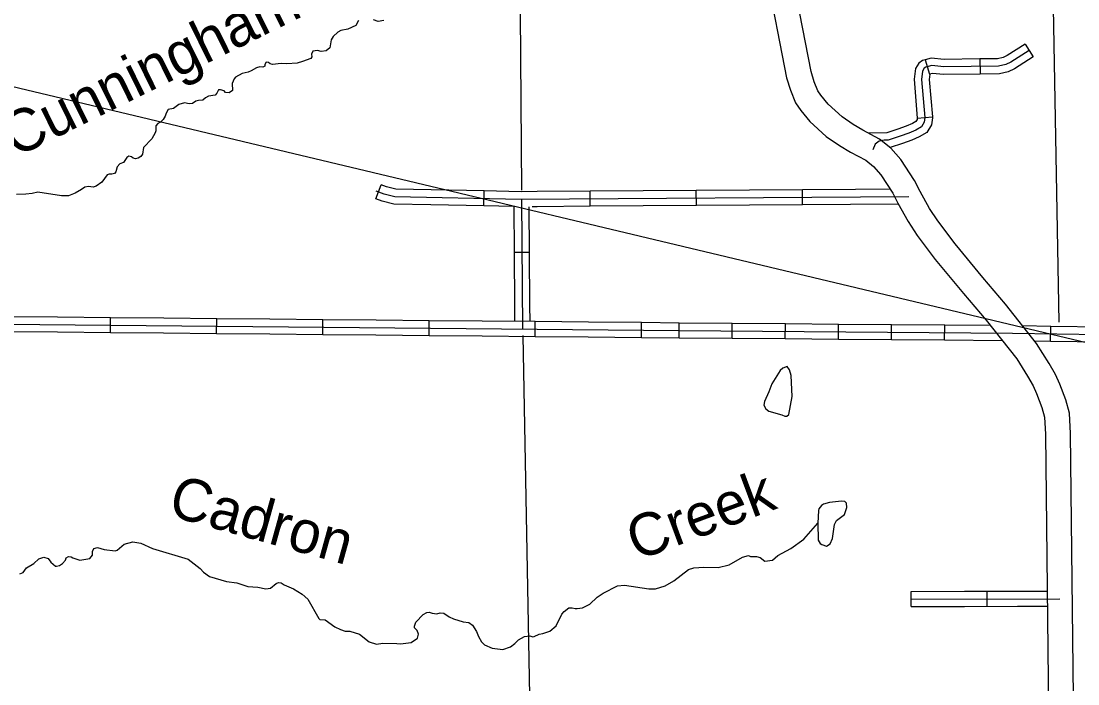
# Model space of a CAD drawing. Extents: x 1212896 to 1368412, y 378476 to 478763.
# Drawn here: x 1289328 to 1299837, y 397540 to 404131 of the extents above; entities that cross this region are included whole.
import ezdxf

# ---------------------------------------------------------------- set-up
doc = ezdxf.new("R2010")
doc.units = 0
for name, color, linetype in [('Level 10', 7, 'Continuous'), ('Level 32', 7, 'Continuous'), ('Level 35', 7, 'Continuous'), ('Level 45', 7, 'Continuous'), ('Level 5', 7, 'Continuous'), ('R_Draft', 7, 'Continuous')]:
    doc.layers.add(name, color=color, linetype=linetype)

msp = doc.modelspace()

# ---------------------------------------------------------------- linework, layer by layer
at = {"layer": 'Level 10'}
for points in [[(1296737, 404612), (1296940, 403569), (1296979, 403444), (1297028, 403318), (1297081, 403243), (1297170, 403134), (1297335, 402985), (1297466, 402894), (1297574, 402829), (1297727, 402748), (1297803, 402687), (1297877, 402602), (1297996, 402422), (1298046, 402321), (1298148, 402139), (1298240, 402000), (1298419, 401761), (1298698, 401422), (1298924, 401159), (1299228, 400772)], [(1299425, 400926), (1299118, 401318), (1298890, 401583), (1298615, 401915), (1298445, 402144), (1298362, 402269), (1298267, 402438), (1298213, 402546), (1298077, 402754), (1297976, 402868), (1297865, 402957), (1297698, 403047), (1297602, 403104), (1297491, 403181), (1297352, 403307), (1297280, 403395), (1297250, 403437), (1297215, 403526), (1297183, 403629), (1296984, 404650)], [(1299830, 394202), (1299764, 400031), (1299753, 400234), (1299716, 400365), (1299658, 400522), (1299615, 400617), (1299551, 400728), (1299425, 400926)], [(1299228, 400772), (1299337, 400599), (1299392, 400503), (1299426, 400427), (1299478, 400288), (1299505, 400193), (1299514, 400023), (1299579, 394212)]]:
    msp.add_lwpolyline(points, dxfattribs=at)
at = {"layer": 'Level 32'}
for p, q in [((1299311, 403902), (1299392, 403776)), ((1298317, 403747), (1298360, 403603)), ((1298863, 403755), (1298865, 403605)), ((1298240, 403167), (1298390, 403180)), ((1295871, 400982), (1295872, 401132)), ((1296399, 400978), (1296400, 401128)), ((1296927, 400974), (1296928, 401124)), ((1297455, 400969), (1297456, 401119)), ((1297983, 400965), (1297984, 401115)), ((1298511, 400961), (1298512, 401111)), ((1299566, 400949), (1299568, 401099))]:
    msp.add_line(p, q, dxfattribs=at)
for points in [[(1299311, 403902), (1299134, 403789), (1299094, 403770), (1299038, 403757), (1298863, 403755)], [(1299351, 403840), (1299169, 403724), (1299119, 403700), (1299047, 403683), (1298504, 403678), (1298384, 403690), (1298323, 403672), (1298309, 403662), (1298293, 403635), (1298281, 403552), (1298314, 403172), (1298307, 403126), (1298280, 403080), (1298224, 403047), (1298156, 403017), (1298069, 402987), (1297949, 402948), (1297909, 402947), (1297862, 402939), (1297820, 402907), (1297796, 402852)], [(1298863, 403755), (1298508, 403751), (1298377, 403764), (1298317, 403747)], [(1299392, 403776), (1299206, 403657), (1299144, 403628), (1299056, 403607), (1298865, 403605)], [(1298317, 403747), (1298291, 403739), (1298254, 403714), (1298222, 403660), (1298207, 403554), (1298240, 403167)], [(1298366, 403605), (1298358, 403550), (1298390, 403180)], [(1298865, 403605), (1298501, 403601), (1298391, 403612), (1298360, 403603)], [(1298240, 403174), (1298237, 403152), (1298226, 403134), (1298191, 403113), (1298129, 403086), (1298045, 403056), (1297937, 403022), (1297751, 403018)], [(1298390, 403180), (1298391, 403169), (1298381, 403100), (1298335, 403024), (1298259, 402979), (1298185, 402946), (1298093, 402914), (1297971, 402875)], [(1295872, 401132), (1296400, 401128)], [(1295871, 401056), (1299186, 401029), (1300949, 401001), (1304662, 400960), (1304738, 400984), (1304788, 400988), (1304879, 400977), (1304930, 400959), (1304962, 400921), (1304984, 400851)], [(1296400, 401128), (1296928, 401124)], [(1296928, 401124), (1297456, 401119)], [(1297456, 401119), (1297984, 401115)], [(1297984, 401115), (1298512, 401111)], [(1298512, 401111), (1298965, 401107)], [(1299286, 401103), (1299568, 401099)], [(1299568, 401099), (1300096, 401091)], [(1295871, 400982), (1296399, 400978)], [(1296399, 400978), (1296927, 400974)], [(1296927, 400974), (1297455, 400969)], [(1297455, 400969), (1297983, 400965)], [(1297983, 400965), (1298511, 400961)], [(1298511, 400961), (1299084, 400956)], [(1299408, 400951), (1299566, 400949)], [(1299566, 400949), (1300094, 400941)]]:
    msp.add_lwpolyline(points, dxfattribs=at)
at = {"layer": 'Level 35'}
for points in [[(1292684, 404136), (1292657, 404088), (1292578, 404050), (1292508, 404038), (1292477, 404023), (1292431, 403978), (1292412, 403946), (1292399, 403866), (1292362, 403835), (1292311, 403830), (1292276, 403838), (1292229, 403831), (1292216, 403803), (1292218, 403775), (1292210, 403760), (1292126, 403731)], [(1292936, 404137), (1292878, 404126), (1292832, 404144)], [(1292126, 403731), (1292072, 403714), (1291971, 403705), (1291914, 403710), (1291828, 403701), (1291804, 403706), (1291787, 403720), (1291764, 403722), (1291751, 403701), (1291751, 403682), (1291731, 403672), (1291701, 403677), (1291667, 403667), (1291615, 403636), (1291585, 403623), (1291527, 403612), (1291458, 403574), (1291445, 403556), (1291426, 403510), (1291428, 403441), (1291395, 403418), (1291361, 403422), (1291345, 403438), (1291309, 403449), (1291290, 403447), (1291275, 403414), (1291258, 403396), (1291190, 403385), (1291161, 403370), (1291135, 403346), (1291093, 403343), (1291065, 403334), (1291032, 403313), (1290998, 403310), (1290951, 403318), (1290896, 403303), (1290844, 403263), (1290790, 403254), (1290770, 403217), (1290761, 403185), (1290741, 403152), (1290713, 403126), (1290686, 403112), (1290668, 403089), (1290666, 403040), (1290660, 403022), (1290626, 402961), (1290543, 402873), (1290534, 402809), (1290517, 402786), (1290493, 402768), (1290466, 402762), (1290443, 402767), (1290425, 402781), (1290399, 402788), (1290380, 402775), (1290346, 402727), (1290310, 402711), (1290284, 402683), (1290270, 402633), (1290257, 402615), (1290230, 402608), (1290203, 402611), (1290183, 402602), (1290131, 402530), (1290075, 402489), (1290043, 402481), (1289996, 402487), (1289960, 402479), (1289929, 402456), (1289866, 402421), (1289800, 402395), (1289728, 402395), (1289494, 402429), (1289436, 402417), (1289375, 402411), (1289282, 402408)], [(1296946, 400695), (1296904, 400679), (1296876, 400657), (1296792, 400525), (1296763, 400446), (1296719, 400350), (1296713, 400312), (1296732, 400274), (1296762, 400254), (1296893, 400216), (1296922, 400204), (1296942, 400204), (1296962, 400218), (1296995, 400399), (1296987, 400606), (1296968, 400664), (1296946, 400695)], [(1297256, 399266), (1297251, 399138), (1297255, 398970), (1297273, 398938), (1297292, 398925), (1297337, 398911), (1297374, 398933), (1297395, 398986), (1297416, 399127), (1297437, 399165), (1297515, 399224), (1297538, 399295), (1297535, 399339), (1297519, 399355), (1297487, 399356), (1297367, 399345), (1297307, 399327), (1297286, 399315), (1297262, 399282), (1297256, 399266)], [(1293238, 398115), (1293254, 398153), (1293327, 398230), (1293361, 398250), (1293385, 398253), (1293416, 398242), (1293462, 398238), (1293495, 398246), (1293530, 398245), (1293584, 398207), (1293626, 398186), (1293724, 398159), (1293780, 398151), (1293817, 398125), (1293855, 398061), (1293876, 398010), (1293907, 397958), (1293937, 397927), (1294012, 397894), (1294119, 397882), (1294194, 397909), (1294236, 397941), (1294274, 397978), (1294335, 398013), (1294388, 398018), (1294417, 398009), (1294430, 398010), (1294480, 398034), (1294517, 398042), (1294584, 398066), (1294647, 398119), (1294704, 398233), (1294729, 398259), (1294775, 398295), (1294806, 398298), (1294836, 398289), (1294857, 398289), (1294911, 398298), (1294984, 398334), (1295057, 398403), (1295115, 398444), (1295258, 398517), (1295329, 398523), (1295571, 398486), (1295635, 398487), (1295731, 398517), (1295819, 398566), (1295965, 398678), (1296019, 398694), (1296118, 398702), (1296261, 398699), (1296370, 398724), (1296501, 398802), (1296560, 398817), (1296582, 398806), (1296642, 398806), (1296676, 398797), (1296724, 398762), (1296799, 398771), (1296854, 398817), (1296983, 398886), (1297112, 398981), (1297251, 399138)], [(1289315, 398636), (1289348, 398648), (1289382, 398693), (1289454, 398736), (1289502, 398783), (1289553, 398802), (1289596, 398787), (1289624, 398752), (1289668, 398712), (1289679, 398712), (1289709, 398718), (1289740, 398738), (1289768, 398772), (1289777, 398794), (1289800, 398808), (1289826, 398804), (1289843, 398793), (1289912, 398771), (1290010, 398787), (1290038, 398822), (1290038, 398857), (1290049, 398888), (1290087, 398897), (1290152, 398878), (1290263, 398862), (1290281, 398869), (1290353, 398929), (1290439, 398952), (1290519, 398939), (1290634, 398888), (1290990, 398780), (1291108, 398687), (1291142, 398651), (1291201, 398609), (1291369, 398558), (1291474, 398544), (1291581, 398509), (1291680, 398501), (1291760, 398486), (1291808, 398491), (1291863, 398537), (1291887, 398549), (1291912, 398546), (1291942, 398527), (1292036, 398487), (1292124, 398433), (1292179, 398384), (1292287, 398189), (1292298, 398179), (1292351, 398176), (1292447, 398109), (1292504, 398081), (1292550, 398065), (1292596, 398063), (1292693, 398035), (1292787, 397959), (1292862, 397936), (1292925, 397945), (1293065, 397943), (1293101, 397937), (1293206, 397951), (1293268, 397995), (1293280, 398036), (1293267, 398070), (1293241, 398098), (1293238, 398115)]]:
    msp.add_lwpolyline(points, dxfattribs=at)
at = {"layer": 'Level 45'}
for p, q in [((1292856, 402363), (1292908, 402504)), ((1293929, 402293), (1293932, 402443)), ((1294987, 402290), (1294986, 402440)), ((1296043, 402297), (1296042, 402447)), ((1297099, 402304), (1297098, 402454)), ((1294381, 401831), (1294231, 401830)), ((1290216, 401035), (1290217, 401185)), ((1291272, 401025), (1291273, 401175)), ((1292328, 401015), (1292329, 401165)), ((1293384, 401005), (1293385, 401155)), ((1294440, 400996), (1294441, 401146)), ((1295496, 400986), (1295497, 401136)), ((1298180, 398310), (1298180, 398460)), ((1298933, 398313), (1298933, 398463))]:
    msp.add_line(p, q, dxfattribs=at)
for points in [[(1293404, 402453), (1293054, 402461), (1292961, 402484), (1292908, 402504)], [(1298154, 402384), (1294301, 402359), (1293044, 402384), (1292939, 402411), (1292859, 402441)], [(1293932, 402443), (1293404, 402453)], [(1294458, 402436), (1294301, 402435), (1293932, 402443)], [(1294986, 402440), (1294458, 402436)], [(1295514, 402443), (1294986, 402440)], [(1296042, 402447), (1295514, 402443)], [(1296570, 402450), (1296042, 402447)], [(1297098, 402454), (1296570, 402450)], [(1297626, 402457), (1297098, 402454)], [(1297971, 402459), (1297626, 402457)], [(1293401, 402303), (1293034, 402311), (1292917, 402341), (1292856, 402363)], [(1293929, 402293), (1293401, 402303)], [(1294228, 402287), (1293929, 402293)], [(1294228, 402287), (1294231, 401830)], [(1294304, 402359), (1294312, 401069)], [(1294459, 402286), (1294411, 402286)], [(1294987, 402290), (1294459, 402286)], [(1295515, 402293), (1294987, 402290)], [(1296043, 402297), (1295515, 402293)], [(1296571, 402300), (1296043, 402297)], [(1297099, 402304), (1296571, 402300)], [(1298052, 402310), (1297099, 402304)], [(1294378, 402286), (1294381, 401831)], [(1294231, 401830), (1294234, 401302)], [(1294381, 401831), (1294384, 401303)], [(1294234, 401302), (1294235, 401148)], [(1294384, 401303), (1294385, 401146)], [(1289161, 401194), (1289689, 401190)], [(1289689, 401190), (1290217, 401185)], [(1290217, 401185), (1290745, 401180)], [(1290745, 401180), (1291273, 401175)], [(1291273, 401175), (1291801, 401170)], [(1291801, 401170), (1292329, 401165)], [(1292329, 401165), (1292857, 401160)], [(1292857, 401160), (1293385, 401155)], [(1293385, 401155), (1293913, 401151)], [(1293913, 401151), (1294441, 401146)], [(1294441, 401146), (1294969, 401141)], [(1294969, 401141), (1295497, 401136)], [(1295497, 401136), (1295872, 401132)], [(1289160, 401118), (1295871, 401056)], [(1289160, 401045), (1289688, 401040)], [(1289688, 401040), (1290216, 401035)], [(1290216, 401035), (1290744, 401030)], [(1290744, 401030), (1291272, 401025)], [(1291272, 401025), (1291800, 401020)], [(1291800, 401020), (1292328, 401015)], [(1292328, 401015), (1292856, 401010)], [(1292856, 401010), (1293384, 401005)], [(1293384, 401005), (1293912, 401001)], [(1293912, 401001), (1294440, 400996)], [(1294440, 400996), (1294968, 400991)], [(1294968, 400991), (1295496, 400986)], [(1295496, 400986), (1295871, 400982)], [(1298180, 398460), (1298708, 398461)], [(1298708, 398461), (1299236, 398463)], [(1299236, 398463), (1299531, 398463)], [(1298180, 398384), (1299658, 398387)], [(1298180, 398310), (1298708, 398311)], [(1298708, 398311), (1299236, 398313)], [(1299236, 398313), (1299533, 398313)]]:
    msp.add_lwpolyline(points, dxfattribs=at)
at = {"layer": 'Level 5'}
for points in [[(1294273, 406418), (1294304, 402451)], [(1299554, 406293), (1299647, 401139)], [(1294316, 401004), (1294385, 397243)]]:
    msp.add_lwpolyline(points, dxfattribs=at)
at = {"layer": 'R_Draft'}
msp.add_line((1324691, 395024), (1283955, 404739), dxfattribs=at)

# ---------------------------------------------------------------- texts
at = {"layer": 'Level 35'}
for s, rotation, p in [('Cunningham', 26.2143, (1289268, 402770)), ('Cadron', 344.4399, (1290774, 399219)), ('Creek', 20.4169, (1295448, 398762))]:
    msp.add_text(s, height=422.4, rotation=rotation, dxfattribs=at).set_placement(p)

doc.saveas('drawing.dxf')
